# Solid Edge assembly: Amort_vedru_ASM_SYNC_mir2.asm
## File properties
Author: KULL
Template: Iso Metric Assembly.asm
Last saved by: KULL
Revision: 2
Application: Solid Edge
Username: KULL
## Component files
Amort_sync.par
vedru__sync_mir2.par
Amort_vedru_ASM_SYNC.asm
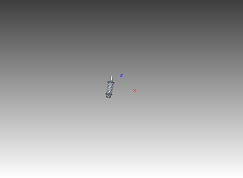
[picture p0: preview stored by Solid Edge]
